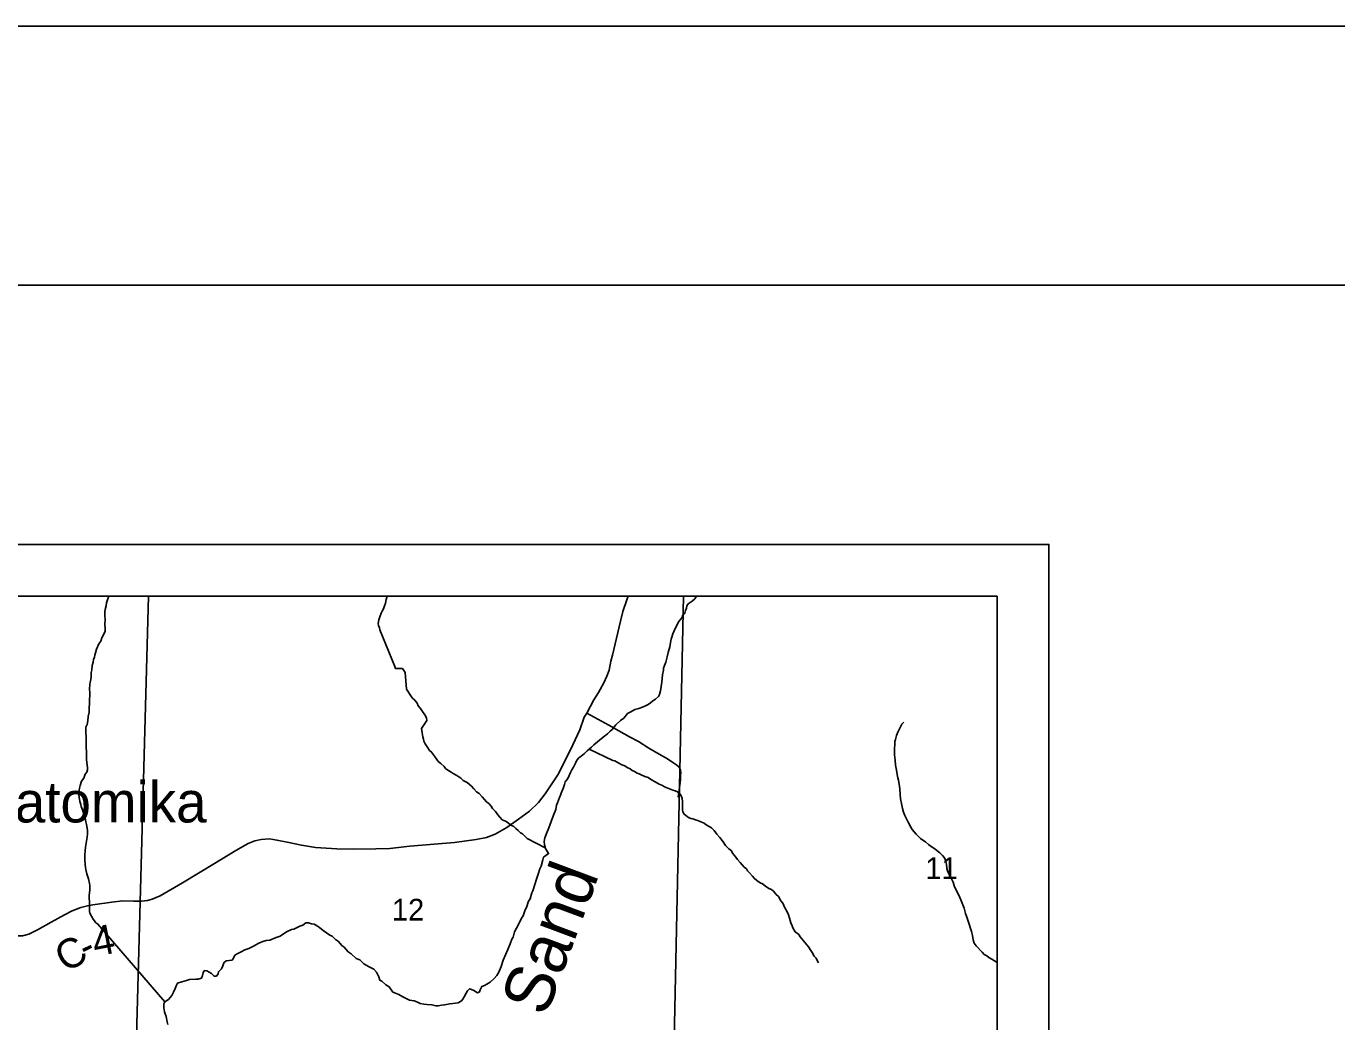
# Model space of a CAD drawing. Extents: x 0 to 34, y 0 to 22.
# Drawn here: x 28.944 to 31.472, y 20.079 to 22 of the extents above; entities that cross this region are included whole.
import ezdxf

# ---------------------------------------------------------------- set-up
doc = ezdxf.new("R2010")
doc.units = 0
for name, color, linetype in [('GM_X_Adjacent_County', 7, 'Continuous'), ('GM_X_County', 7, 'Continuous'), ('GM_X_County_Road', 7, 'Continuous'), ('GM_X_County_Road_Text', 7, 'Continuous'), ('GM_X_Minor_River', 7, 'Continuous'), ('GM_X_Minor_River_Text', 7, 'Continuous'), ('GM_X_Section', 7, 'Continuous'), ('GM_X_Section_Text', 7, 'Continuous'), ('GM_X_Township', 7, 'Continuous'), ('GM_X_Township_Road', 7, 'Continuous'), ('GM_X_Unincorporated_Text', 7, 'Continuous'), ('SH_Border', 7, 'Continuous'), ('SH_Cut_Line', 7, 'Continuous'), ('SH_Data', 7, 'Continuous')]:
    doc.layers.add(name, color=color, linetype=linetype)

msp = doc.modelspace()

# ---------------------------------------------------------------- linework, layer by layer
at = {"layer": 'GM_X_Adjacent_County'}
msp.add_lwpolyline([(30.8167, 17.8174), (30.8167, 20.9), (24.0167, 20.9), (24.0167, 18.0693)], dxfattribs=at)
at = {"layer": 'GM_X_County'}
msp.add_lwpolyline([(30.8167, 17.8174), (30.8167, 20.9), (24.0167, 20.9), (24.0167, 18.0693)], dxfattribs=at)
at = {"layer": 'GM_X_County_Road'}
for points in [[(30.105, 20.9), (30.1025, 20.893), (30.095, 20.8704), (30.0903, 20.852), (30.0753, 20.7862), (30.0721, 20.7745), (30.0683, 20.757), (30.0642, 20.7459), (30.0585, 20.733), (30.0483, 20.7144), (30.0393, 20.6999), (30.0252, 20.6745), (30.0206, 20.6663), (30.0118, 20.6419), (29.9939, 20.6034), (29.9697, 20.5555), (29.945, 20.5188), (29.9323, 20.5018), (29.9148, 20.4855), (29.8935, 20.4697), (29.8709, 20.454), (29.8485, 20.4407), (29.8317, 20.4343), (29.8122, 20.4307), (29.7703, 20.4248), (29.6842, 20.4175), (29.6454, 20.4132), (29.6184, 20.4128), (29.5745, 20.4119), (29.5432, 20.4128), (29.502, 20.4153), (29.475, 20.4194), (29.4473, 20.4252), (29.4276, 20.4293), (29.4131, 20.4316), (29.3975, 20.4305), (29.3848, 20.4277), (29.3723, 20.423), (29.3483, 20.4092), (29.3071, 20.384), (29.2454, 20.3468), (29.2024, 20.3217), (29.1872, 20.3151), (29.1781, 20.3126), (29.1663, 20.3115), (29.1509, 20.3115), (29.1305, 20.3119), (29.1092, 20.3097), (29.0727, 20.3047), (29.0625, 20.3024)], [(29.0625, 20.3024), (29.0496, 20.2995), (29.0331, 20.2929), (29.0181, 20.2854), (28.9923, 20.2709), (28.966, 20.2562), (28.9492, 20.2478), (28.9371, 20.2448), (28.9247, 20.2448), (28.9132, 20.2467), (28.8919, 20.2531), (28.8483, 20.268), (28.8098, 20.2823), (28.7859, 20.2905), (28.7722, 20.295), (28.7571, 20.3003)]]:
    msp.add_lwpolyline(points, dxfattribs=at)
at = {"layer": 'GM_X_Minor_River'}
for points in [[(29.2118, 20.1174), (29.0825, 20.2673), (29.0787, 20.2696), (29.0756, 20.2734), (29.0734, 20.2771), (29.0699, 20.2825), (29.0669, 20.2881), (29.0665, 20.2919), (29.0665, 20.306), (29.0661, 20.3116), (29.0657, 20.3162), (29.0656, 20.323), (29.0664, 20.3276), (29.0667, 20.3333), (29.0667, 20.3416), (29.066, 20.3458), (29.064, 20.3549), (29.061, 20.3643), (29.0594, 20.3727), (29.0583, 20.3765), (29.0579, 20.3825), (29.0571, 20.392), (29.0571, 20.3962), (29.0575, 20.4007), (29.0578, 20.4087), (29.0585, 20.4155), (29.0593, 20.4193), (29.0615, 20.4353), (29.0626, 20.4417), (29.0626, 20.4485), (29.0607, 20.4595), (29.0592, 20.4645), (29.0576, 20.4717), (29.0557, 20.4758), (29.0542, 20.4834), (29.053, 20.488), (29.0503, 20.4944), (29.0492, 20.4982), (29.0477, 20.5039), (29.0461, 20.5122), (29.0454, 20.5168), (29.0457, 20.5213), (29.0461, 20.5259), (29.0468, 20.5297), (29.0483, 20.5346), (29.051, 20.543), (29.0551, 20.5486), (29.0581, 20.5566), (29.0608, 20.5604), (29.0626, 20.565), (29.0626, 20.5688), (29.0618, 20.5748), (29.0611, 20.5794), (29.0607, 20.5851), (29.0607, 20.5892), (29.059, 20.6473), (29.0616, 20.6522), (29.0627, 20.6594), (29.0638, 20.6681), (29.0653, 20.6765), (29.0653, 20.6818), (29.0657, 20.6856), (29.066, 20.6917), (29.0664, 20.7015), (29.0668, 20.708), (29.0667, 20.7144), (29.0663, 20.7209), (29.0671, 20.7296), (29.0674, 20.7334), (29.0686, 20.7395), (29.0693, 20.7451), (29.0697, 20.7493), (29.0696, 20.7531), (29.0704, 20.758), (29.0715, 20.7664), (29.0734, 20.7728), (29.0741, 20.7781), (29.0756, 20.7823), (29.0764, 20.7865), (29.0779, 20.7907), (29.0794, 20.7979), (29.0843, 20.8078), (29.088, 20.8135), (29.0899, 20.8195), (29.0948, 20.8279), (29.0963, 20.8324), (29.0963, 20.8385), (29.0959, 20.8457), (29.0962, 20.8556), (29.0958, 20.8624), (29.0958, 20.8696), (29.0962, 20.8742), (29.0981, 20.8814), (29.0992, 20.8874), (29.1014, 20.895), (29.1032, 20.9)], [(29.9454, 20.4142), (29.9107, 20.4323), (29.9065, 20.4361), (29.9012, 20.4414), (29.8974, 20.4437), (29.8928, 20.4478), (29.8886, 20.4516), (29.8848, 20.4554), (29.8791, 20.4584), (29.8735, 20.4626), (29.8685, 20.4656), (29.8624, 20.4686), (29.8575, 20.4739), (29.8541, 20.4781), (29.8491, 20.4845), (29.8438, 20.4902), (29.8408, 20.4948), (29.8366, 20.4997), (29.832, 20.5035), (29.8282, 20.508), (29.8233, 20.5126), (29.8176, 20.519), (29.813, 20.5224), (29.8073, 20.5285), (29.8028, 20.5334), (29.7948, 20.5402), (29.7868, 20.5447), (29.7826, 20.5489), (29.7747, 20.5542), (29.7674, 20.5576), (29.7636, 20.5606), (29.7576, 20.5644), (29.7526, 20.5678), (29.75, 20.5716), (29.7439, 20.5769), (29.739, 20.581), (29.7363, 20.5848), (29.7317, 20.5913), (29.726, 20.5992), (29.7222, 20.6023), (29.7188, 20.6072), (29.7165, 20.6113), (29.7135, 20.6151), (29.7112, 20.6204), (29.7104, 20.6242), (29.7093, 20.6284), (29.7081, 20.6364), (29.7066, 20.6447), (29.7171, 20.6599), (29.716, 20.6652), (29.7129, 20.6709), (29.7087, 20.6773), (29.7049, 20.6834), (29.7004, 20.6887), (29.6985, 20.6936), (29.6939, 20.6993), (29.6893, 20.7035), (29.6863, 20.708), (29.6836, 20.7118), (29.6802, 20.7167), (29.6775, 20.7205), (29.6752, 20.7527), (29.6725, 20.7569), (29.6698, 20.7607), (29.6641, 20.7603), (29.6566, 20.7603), (29.655, 20.7641), (29.626, 20.835), (29.6253, 20.8387), (29.6237, 20.8433), (29.6233, 20.8475), (29.6245, 20.8543), (29.6263, 20.8604), (29.629, 20.8672), (29.6309, 20.871), (29.6331, 20.8759), (29.635, 20.8812), (29.6369, 20.8869), (29.6387, 20.8934), (29.6399, 20.8976), (29.6403, 20.9)], [(30.2371, 20.9), (30.2337, 20.8949), (30.2287, 20.8904), (30.2212, 20.8854), (30.2182, 20.8816), (30.2178, 20.8771), (30.2159, 20.8725), (30.2144, 20.8672), (30.2103, 20.8634), (30.2095, 20.8592), (30.2057, 20.8547), (30.2027, 20.8509), (30.1982, 20.8429), (30.194, 20.8334), (30.1914, 20.8273), (30.1895, 20.8209), (30.1884, 20.8171), (30.1869, 20.8106), (30.1854, 20.8023), (30.1824, 20.7916), (30.1806, 20.7829), (30.1779, 20.7727), (30.1753, 20.7662), (30.1734, 20.7609), (30.1731, 20.7571), (30.1716, 20.7484), (30.1701, 20.734), (30.169, 20.726), (30.1675, 20.7173), (30.1656, 20.7104), (30.1637, 20.7066), (30.1581, 20.7013), (30.1531, 20.6983), (30.1486, 20.6945), (30.1437, 20.6911), (30.1388, 20.6884), (30.1327, 20.6861), (30.1255, 20.6831), (30.118, 20.6811), (30.1104, 20.6766), (30.104, 20.6739), (30.0968, 20.6644), (30.0904, 20.6599), (30.0813, 20.6519), (30.0745, 20.6431), (30.0703, 20.6393), (30.0651, 20.6344), (30.0571, 20.6283), (30.039, 20.6135), (30.0348, 20.6089), (30.0307, 20.6055), (30.0261, 20.6017), (30.0208, 20.5968), (30.0148, 20.5914), (30.0102, 20.588), (30.0065, 20.5835), (30.0042, 20.5793), (30.0001, 20.5698), (29.9963, 20.5652), (29.9937, 20.5599), (29.9895, 20.5497), (29.9869, 20.5455), (29.9839, 20.5417), (29.9827, 20.5368), (29.9805, 20.5311), (29.9763, 20.5201), (29.9745, 20.5163), (29.973, 20.5117), (29.9688, 20.5011), (29.9673, 20.4965), (29.9655, 20.4886), (29.9613, 20.4776), (29.9568, 20.465), (29.9519, 20.4529)], [(30.6788, 20.4259), (30.6735, 20.4293), (30.6693, 20.4327), (30.6644, 20.4368), (30.6606, 20.4406), (30.6571, 20.4452), (30.6529, 20.4501), (30.6503, 20.4543), (30.6457, 20.463), (30.643, 20.469), (30.6388, 20.4766), (30.6362, 20.4831), (30.6343, 20.4903), (30.6327, 20.5001), (30.6308, 20.5092), (30.63, 20.5172), (30.6292, 20.5282), (30.6284, 20.5327), (30.6265, 20.5452), (30.6257, 20.5494), (30.6242, 20.5562), (30.6227, 20.5646), (30.6211, 20.574), (30.6203, 20.5839), (30.6192, 20.5938), (30.6191, 20.6048), (30.6195, 20.615), (30.6198, 20.6196), (30.6206, 20.6237), (30.6228, 20.6309), (30.6255, 20.6378), (30.6277, 20.6427), (30.6296, 20.6465), (30.6334, 20.6533), (30.6372, 20.6571)], [(30.0302, 20.6051), (30.0754, 20.5832), (30.0792, 20.5821), (30.083, 20.5802), (30.0883, 20.5772), (30.0929, 20.5749), (30.0986, 20.5726), (30.1035, 20.5696), (30.1088, 20.567), (30.113, 20.5639), (30.1176, 20.5617), (30.1225, 20.5587), (30.1263, 20.5575), (30.1301, 20.5553), (30.1373, 20.5522), (30.1437, 20.55), (30.1502, 20.5458), (30.157, 20.5417), (30.165, 20.5371), (30.1714, 20.5349), (30.1756, 20.5322), (30.1817, 20.5296), (30.1912, 20.5258), (30.1957, 20.5247), (30.2007, 20.5224), (30.2056, 20.5182), (30.2083, 20.5133), (30.2094, 20.5095), (30.2098, 20.5038), (30.2098, 20.4925), (30.2102, 20.4875), (30.2106, 20.4837), (30.2133, 20.4796), (30.2217, 20.4728), (30.2258, 20.4709), (30.23, 20.4701), (30.2353, 20.4682), (30.2399, 20.4671), (30.2456, 20.4645), (30.252, 20.4618), (30.2558, 20.4588), (30.2657, 20.4531), (30.271, 20.4478), (30.2763, 20.441), (30.282, 20.4342), (30.2885, 20.4262), (30.2927, 20.419), (30.2995, 20.4122), (30.3045, 20.4085), (30.3067, 20.4043), (30.3128, 20.3963), (30.3159, 20.3918), (30.3212, 20.3861), (30.325, 20.3816), (30.3292, 20.377), (30.3334, 20.374), (30.3356, 20.3702), (30.3391, 20.366), (30.3448, 20.36), (30.3482, 20.3558), (30.3531, 20.3517), (30.36, 20.3468), (30.3641, 20.3449), (30.3702, 20.3403), (30.3763, 20.3362), (30.3816, 20.3339), (30.3858, 20.3305), (30.3904, 20.3244), (30.3949, 20.3203), (30.3999, 20.3119), (30.4033, 20.3078), (30.4075, 20.2987), (30.4105, 20.2934), (30.4147, 20.2854), (30.4163, 20.279), (30.4189, 20.2699), (30.4216, 20.2642), (30.4231, 20.26), (30.4273, 20.2525), (30.4342, 20.2472), (30.4372, 20.2426), (30.4433, 20.2351), (30.449, 20.2282), (30.4539, 20.2229), (30.4562, 20.218), (30.46, 20.2123), (30.4642, 20.2055), (30.468, 20.2014), (30.4696, 20.1968), (30.4722, 20.1927)], [(29.9519, 20.4529), (29.9474, 20.4419), (29.9448, 20.4335), (29.9433, 20.4267), (29.9441, 20.4203), (29.9456, 20.4131), (29.9494, 20.407), (29.9517, 20.4032), (29.9464, 20.3994), (29.9422, 20.3964), (29.9404, 20.3914), (29.9374, 20.3793), (29.9347, 20.374), (29.9317, 20.3634), (29.9284, 20.3539), (29.9254, 20.344), (29.9212, 20.3315), (29.9193, 20.3273), (29.916, 20.3159), (29.9133, 20.3114), (29.9092, 20.2996), (29.9066, 20.2951), (29.9024, 20.2833), (29.8994, 20.2787), (29.8968, 20.2727), (29.8896, 20.2594), (29.8862, 20.2525), (29.8832, 20.2419), (29.881, 20.2381), (29.8776, 20.2294), (29.8731, 20.2184), (29.8689, 20.2078), (29.8644, 20.1975), (29.8603, 20.1854), (29.8558, 20.1748), (29.8516, 20.1679), (29.8467, 20.1622), (29.8388, 20.155), (29.8327, 20.1516), (29.8282, 20.1489), (29.8229, 20.1466), (29.8195, 20.1406), (29.8187, 20.1368), (29.8146, 20.1349), (29.8078, 20.1394), (29.8028, 20.1413), (29.799, 20.1424), (29.7953, 20.1382), (29.7926, 20.1337), (29.7892, 20.1272), (29.7866, 20.1227), (29.7839, 20.1189), (29.7775, 20.1155), (29.7673, 20.1139), (29.7612, 20.1132), (29.751, 20.1112), (29.7449, 20.1108), (29.7385, 20.1097), (29.7343, 20.1097), (29.7267, 20.1116), (29.7169, 20.1119), (29.7108, 20.1127), (29.704, 20.1138), (29.6979, 20.1172), (29.6922, 20.1191), (29.6835, 20.1202), (29.6782, 20.1232), (29.6706, 20.1266), (29.663, 20.1312), (29.6562, 20.1338), (29.6516, 20.1361), (29.644, 20.1463), (29.638, 20.1501), (29.6304, 20.1569), (29.6262, 20.1588), (29.6243, 20.1652), (29.6197, 20.1743), (29.6144, 20.1804), (29.6045, 20.1856), (29.5954, 20.1906), (29.5878, 20.1981), (29.5806, 20.2011), (29.5711, 20.2099), (29.5654, 20.2136), (29.5574, 20.2227), (29.5529, 20.2261), (29.5456, 20.2341), (29.5415, 20.2371), (29.5342, 20.2439), (29.5297, 20.2462), (29.5236, 20.2503), (29.5171, 20.2549), (29.5099, 20.2609), (29.5061, 20.2632), (29.4993, 20.267), (29.4947, 20.2681), (29.4887, 20.27), (29.4834, 20.27), (29.4777, 20.2654), (29.472, 20.2635), (29.4603, 20.2574)], [(30.8167, 20.1931), (30.8121, 20.1964), (30.8064, 20.1998), (30.8011, 20.2028), (30.7969, 20.2058), (30.792, 20.2088), (30.7878, 20.2134), (30.7764, 20.2255), (30.7726, 20.2304), (30.7707, 20.2372), (30.7691, 20.2452), (30.7672, 20.2528), (30.7653, 20.2588), (30.763, 20.2672), (30.7603, 20.2747), (30.7584, 20.2808), (30.7561, 20.288), (30.7531, 20.2982), (30.7485, 20.3111), (30.7435, 20.3221), (30.7348, 20.3395), (30.7321, 20.3482), (30.729, 20.3547), (30.726, 20.3607), (30.7233, 20.3657), (30.7214, 20.3702), (30.7202, 20.3748), (30.7191, 20.3831), (30.7175, 20.3907), (30.7156, 20.3952), (30.7115, 20.3994), (30.7061, 20.4051), (30.7008, 20.4096), (30.6966, 20.4123), (30.6894, 20.4172), (30.6845, 20.421), (30.6788, 20.4259)], [(29.4603, 20.2574), (29.4558, 20.2566), (29.4459, 20.2525), (29.4338, 20.2437), (29.4262, 20.2414), (29.4138, 20.2365), (29.4073, 20.2353), (29.4005, 20.2334), (29.3929, 20.2304), (29.3827, 20.225), (29.3736, 20.2205), (29.3661, 20.2174), (29.3589, 20.2136), (29.3513, 20.2102), (29.3464, 20.2071), (29.3441, 20.2015), (29.3411, 20.1977), (29.3301, 20.1961), (29.3252, 20.1927), (29.3233, 20.187), (29.3207, 20.1809), (29.315, 20.1752), (29.3143, 20.1711), (29.3109, 20.1665), (29.3064, 20.1665), (29.3014, 20.1718), (29.2923, 20.1771), (29.2881, 20.1778), (29.2855, 20.1737), (29.2844, 20.168), (29.2821, 20.1627), (29.2761, 20.1607), (29.2711, 20.1607), (29.2594, 20.1603), (29.253, 20.1584), (29.2442, 20.1558), (29.2359, 20.1531), (29.234, 20.1493), (29.2314, 20.1432), (29.2284, 20.136), (29.225, 20.1296), (29.2186, 20.122), (29.2118, 20.1174), (29.2099, 20.1132), (29.2095, 20.106), (29.2111, 20.0981), (29.2122, 20.0943), (29.2138, 20.089), (29.2161, 20.0787), (29.2172, 20.0738)]]:
    msp.add_lwpolyline(points, dxfattribs=at)
at = {"layer": 'GM_X_Section'}
for p, q in [((29.18, 20.9), (28.7096, 20.9)), ((30.2122, 20.9), (29.18, 20.9))]:
    msp.add_line(p, q, dxfattribs=at)
for points in [[(28.7096, 20.9), (28.7088, 20.8738), (28.1991, 20.8853), (28.1829, 20.3798), (28.381, 20.3744), (28.6946, 20.3663), (28.6821, 19.9791), (28.6801, 19.9157), (29.153, 19.9086), (29.18, 20.9)], [(29.18, 20.9), (29.153, 19.9086), (30.191, 19.8901), (30.2122, 20.9)], [(30.2122, 20.9), (30.191, 19.8901), (30.8167, 19.8701)], [(30.8167, 19.8701), (30.8167, 20.9), (30.2122, 20.9)]]:
    msp.add_lwpolyline(points, dxfattribs=at)
at = {"layer": 'GM_X_Township'}
msp.add_lwpolyline([(30.8167, 17.8174), (30.8167, 20.9), (26.3564, 20.9)], dxfattribs=at)
at = {"layer": 'GM_X_Township_Road'}
msp.add_lwpolyline([(30.0252, 20.6745), (30.047, 20.663), (30.068, 20.6512), (30.0871, 20.6405), (30.1079, 20.6287), (30.1251, 20.6195), (30.1451, 20.6065), (30.1653, 20.5952), (30.1811, 20.5864), (30.1936, 20.5778), (30.1993, 20.5741), (30.2038, 20.5701), (30.206, 20.5644), (30.2065, 20.5592), (30.2063, 20.5542), (30.2063, 20.5463), (30.2049, 20.5356), (30.2015, 20.5123)], dxfattribs=at)
at = {"layer": 'SH_Border'}
msp.add_lwpolyline([(2, 21.5), (33.5, 21.5), (33.5, 0.5), (2, 0.5)], close=True, dxfattribs=at)
at = {"layer": 'SH_Cut_Line'}
msp.add_lwpolyline([(0, 0), (34, 0), (34, 22), (0, 22)], close=True, dxfattribs=at)
at = {"layer": 'SH_Data'}
for points in [[(23.9167, 21), (30.9167, 21), (30.9167, 14), (23.9167, 14)], [(24.0167, 20.9), (30.8167, 20.9), (30.8167, 14.1), (24.0167, 14.1)]]:
    msp.add_lwpolyline(points, close=True, dxfattribs=at)

# ---------------------------------------------------------------- texts
at = {"layer": 'GM_X_County_Road_Text'}
for s, rotation, p in [('4', 11.1446, (29.0773, 20.2042)), ('C', 29.2453, (29.02, 20.1728)), ('-', 25.9751, (29.06, 20.1952))]:
    msp.add_text(s, height=0.0568, rotation=rotation, dxfattribs=at).set_placement(p)
at = {"layer": 'GM_X_Minor_River_Text'}
msp.add_text('Sand', height=0.09462, rotation=69.4811, dxfattribs=at).set_placement((29.9462, 20.0861))
at = {"layer": 'GM_X_Section_Text'}
for s, p in [('11', (30.6784, 20.3543)), ('12', (29.6496, 20.2742))]:
    msp.add_text(s, height=0.04186, rotation=0, dxfattribs=at).set_placement(p)
at = {"layer": 'GM_X_Unincorporated_Text'}
msp.add_text('Wakatomika', height=0.07898, rotation=0, dxfattribs=at).set_placement((28.7109, 20.4634))

doc.saveas('drawing.dxf')
